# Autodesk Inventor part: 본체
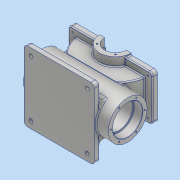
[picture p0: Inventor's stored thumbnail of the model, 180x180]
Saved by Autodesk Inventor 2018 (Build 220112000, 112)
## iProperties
Created: 2023-07
Part Number: 본체
Material: 알루미늄 6061
Document SubType Name: Modeling
Designer: home
Density: 2.7 g/cm^3
Appearance: 알루미늄 - 평지
Mass: 5726.42 g
Surface Area: 2842.33 cm^2
Volume: 2120.9 cm^3
Author: home
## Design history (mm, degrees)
sketch "스케치1"
  geometry: L1 (-100, -100)-(100, -100); L2 (100, -100)-(100, 100); L3 (100, 100)-(-100, 100); L4 (-100, 100)-(-100, -100); L5 (-100, -100)-(100, 100); L6 (100, -100)-(-100, 100); 1 further point
  constraints: 12 end point, 2 midpoint, 2 parallel, 1 horizontal, 1 perpendicular
  dimensions: "d0" = 200 distance of L3.end L2.end; "d1" = 200 distance of L2.end L1.end
extrude "돌출1" new body sketch "스케치1" distance "d2" = 15; taper "d3" = 0 deg
sketch "스케치3"
  geometry: C1 r 55 at (60, 0); 1 further point
  constraints: 1 centre point, 1 horizontal alignment
  dimensions: "d10" = 110 diameter of C1; "d11" = 60 distance of point (0, 0) C1.centre
extrude "돌출3" join sketch "스케치3" distance "d12" = 135; taper "d14" = 0 deg; dims "d13" = 107, "d15" = 0
sketch "스케치4"
  geometry: L1 (-100, 160)-(100, 160); A1 r 100 centre (0, 160) between (-100, 160) and (100, 160); 1 further point
  constraints: 2 end point, 2 point on circle, 1 centre point, 1 horizontal, 1 vertical alignment
  dimensions: "d16" = 200 diameter of A1; "d17" = 160 distance of point (0, 0) A1.centre; "d18" = 160 distance from line of point (0, 0) L1
extrude "돌출4" join sketch "스케치4" distance "d19" = 45; taper "d21" = 0 deg; dims "d20" = 45, "d22" = 0
sketch "스케치5"
  geometry: L1 (-20, 110)-(220, 110); L2 (220, 110)-(220, -20); L3 (220, -20)-(-20, -20); L4 (-20, -20)-(-20, 110); L5 (-20, 110)-(220, -20); L6 (220, 110)-(-20, -20); 1 further point
  constraints: 12 end point, 2 midpoint, 2 parallel, 1 horizontal, 1 perpendicular
  dimensions: "d23" = 240 distance of L2.end L3.end; "d24" = 130 distance of L1.end L2.end
extrude "돌출5" join sketch "스케치5" distance "d25" = 15; taper "d26" = 0 deg
sketch "스케치7"
  geometry: L1 (-120, 160)-(120, 160) reference; L2 (-45, 160)-(45, 160); A1 r 45 centre (0, 160) between (-45, 160) and (45, 160); 1 further point
  constraints: 2 end point, 2 point on circle, 2 point on line, 1 centre point, 1 midpoint
  dimensions: "d32" = 90 diameter of A1
extrude "돌출7" join sketch "스케치7" distance "d33" = 70; taper "d35" = 0 deg; dims "d34" = 70, "d36" = 0
sketch "스케치8"
  geometry: L1 (-45, 160)-(45, 160) reference; C1 r 87 at (0, 160); 1 further point
  constraints: 1 centre point, 1 midpoint
  dimensions: "d37" = 174 diameter of C1
extrude "돌출8" cut sketch "스케치8" distance "d38" = 32; taper "d40" = 0 deg; dims "d39" = 32, "d41" = 0
hole "구멍1" diameter "d44" = 77; stored, may be unused: countersink angle "d48" = 90 deg, drill point angle "d50" = 0 deg; dims "d45" = 6, "d46" = 85, "d47" = 25, "d49" = 192, "d143" = 10, "d144" = 10
sketch "스케치9"
  geometry: 2 further points
  constraints: 1 vertical alignment
  dimensions: "d51" = 108.5 distance of point (0, -60) point (0, 48.5)
hole "구멍2" sketch "스케치9" at (0, 48.5) diameter "d52" = 4.134; stored, may be unused: countersink angle "d56" = 90 deg, drill point angle "d58" = 118 deg; dims "d53" = 10, "d54" = 85, "d55" = 25, "d57" = 12
sketch "스케치10"
  geometry: 2 further points
  dimensions: "d62" = 107 horizontal distance of point (-13, 13) point (-120, 65); "d63" = 52 vertical distance of point (-120, 65) point (-13, 13)
hole "구멍3" sketch "스케치10" at (-13, 13) diameter "d64" = 4.917; stored, may be unused: countersink angle "d68" = 90 deg, drill point angle "d70" = 118 deg; dims "d65" = 15, "d66" = 85, "d67" = 25, "d69" = 15
sketch "스케치11"
  geometry: 2 further points
  dimensions: "d77" = 80 horizontal distance of point (80, -80) point (0, 0); "d78" = 80 horizontal distance of point (0, 0) point (80, -80)
hole "구멍4" sketch "스케치11" at (80, -80) diameter "d79" = 11; stored, may be unused: countersink angle "d83" = 90 deg, drill point angle "d85" = 0 deg; dims "d80" = 12, "d81" = 28, "d82" = 2, "d84" = 15
hole "구멍5" diameter "d94" = 55; stored, may be unused: countersink angle "d98" = 90 deg, drill point angle "d100" = 0 deg; dims "d92" = 10, "d93" = 10, "d95" = 12, "d96" = 62, "d97" = 23, "d99" = 70
sketch "스케치12"
  geometry: L1 (-87, 160)-(87, 160) reference; L2 (0, 160)-(26.163, 133.837); L3 (0, 160)-(37, 160); L4 (0, 160)-(0, 150); L5 (0, 160)-(-26.163, 133.837); 3 further points
  constraints: 8 end point, 2 coincident, 2 symmetric about line, 1 equal length, 1 horizontal, 1 midpoint, 1 vertical
  dimensions: "d101" = 37 distance of L2.start L2.end; "d102" = 45 deg angle of L2 L3; "d103" = 10 distance of L2.start L4.end
hole "구멍6" sketch "스케치12" at (26.163, 133.837), (-26.163, 133.837) diameter "d104" = 4.134; stored, may be unused: countersink angle "d108" = 90 deg, drill point angle "d110" = 118 deg; dims "d105" = 10, "d106" = 62, "d107" = 23, "d109" = 12
fillet "모깎기1" dims "d111" = 15, "d112" = 10, "d113" = 10, "d114" = 1, "d115" = 1.1, "d116" = 3, "d117" = 3, "d118" = 3, "d119" = 3, "d120" = 3, "d121" = 3, "d125" = 3
sketch "스케치13"
  geometry: L1 (-90, -100)-(90, -100) reference; 2 further points
  constraints: 1 vertical alignment, 1 other
  dimensions: "d126" = 15 distance from line of L1 point (0, -85)
feature "엠보싱1" sketch "스케치13" dims "d0" = 200, "d1" = 200, "d127" = 0.5, "d128" = 0
hole "구멍7" diameter "d136" = 85; stored, may be unused: countersink angle "d140" = 90 deg, drill point angle "d142" = 0 deg; dims "d137" = 10, "d138" = 85, "d139" = 25, "d141" = 25, "d145" = 10, "d146" = 10
sketch "스케치14"
  geometry: C1 r 2.067 at (0, 48.5) reference; 2 further points
  constraints: 1 coincident
hole "구멍8" sketch "스케치14" at (0, 48.5) diameter "d147" = 4.134; stored, may be unused: countersink angle "d151" = 90 deg, drill point angle "d153" = 118 deg; dims "d148" = 10, "d149" = 4, "d150" = 25, "d152" = 12
fillet "모깎기2" dims "d157" = 1.1, "d161" = 3, "d162" = 3, "d163" = 3
chamfer "모따기2" distance "d158" = 1; stored, may be unused: second distance "d159" = 2, angle "d160" = 45 deg
node "솔리드1"
pattern_linear "직사각형 패턴1" dims "d73" = 104, "d76" = 214
pattern_linear "직사각형 패턴2" dims "d88" = 160, "d91" = 160
mirror "미러2"
pattern_circular "원형 패턴2" dims angle "d132" = 360 deg
pattern_circular "원형 패턴3" dims angle "d155" = 360 deg
